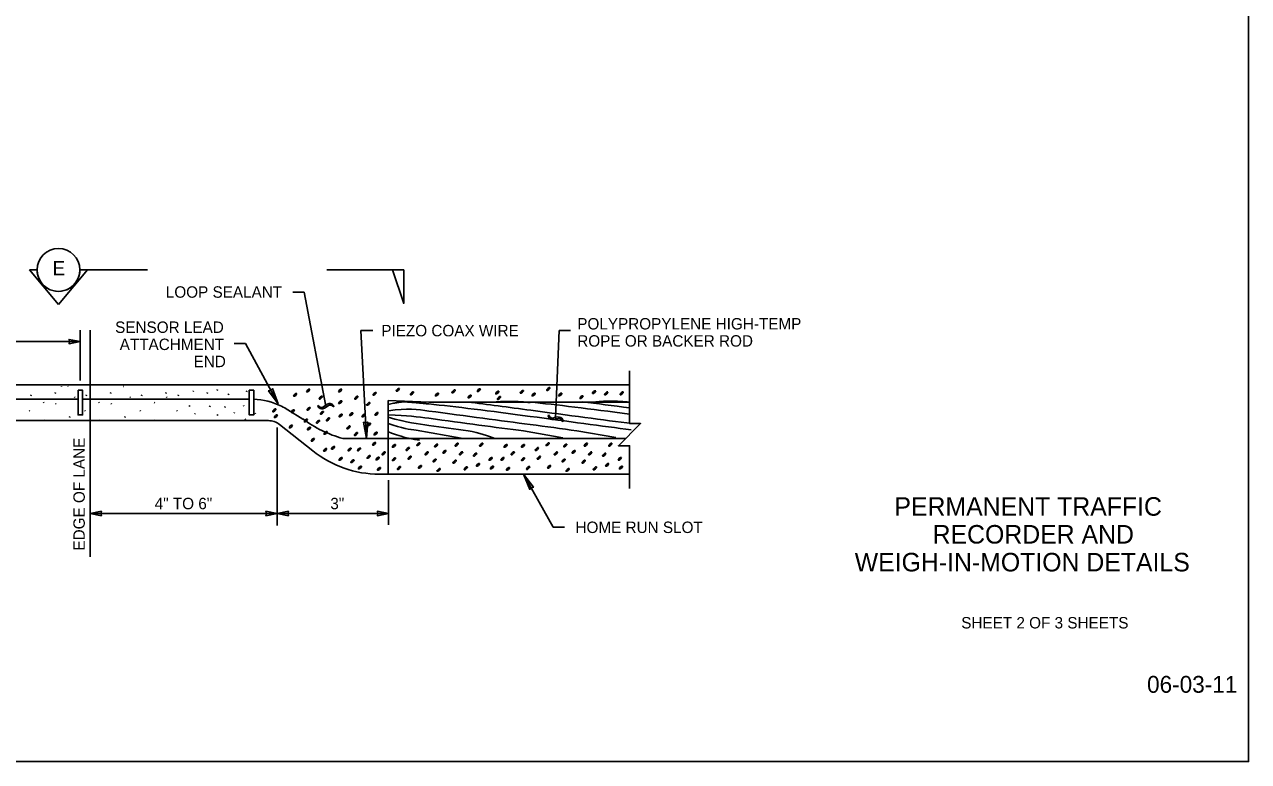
# Model space of a CAD drawing. Extents: x 99862 to 103151, y 100000 to 108076.
# Drawn here: x 101437 to 103151, y 103000 to 104032 of the extents above; entities that cross this region are included whole.
import ezdxf

# ---------------------------------------------------------------- set-up
doc = ezdxf.new("R2010")
doc.units = 0
for name, color, linetype in [('Level 1', 7, 'Continuous'), ('Level 15', 7, 'Continuous'), ('Level 16', 7, 'Continuous'), ('Level 2', 7, 'Continuous'), ('Level 20', 7, 'Continuous'), ('Level 32', 7, 'Continuous'), ('Level 33', 7, 'Continuous'), ('Level 5', 7, 'Continuous'), ('Level 6', 7, 'Continuous'), ('Level 62', 7, 'Continuous'), ('Level 9', 7, 'Continuous')]:
    doc.layers.add(name, color=color, linetype=linetype)

msp = doc.modelspace()

# ---------------------------------------------------------------- linework, layer by layer
at = {"layer": 'Level 1'}
msp.add_lwpolyline([(99862, 102999.5), (103151, 102999.5), (103151, 105075.5), (99862, 105075.5)], close=True, dxfattribs=at)
at = {"layer": 'Level 15'}
for p, q in [((101828.2, 103657), (101812.2, 103657)), ((101828.2, 103657), (101858.6, 103497.2)), ((101514.7, 103603.8), (101514.7, 103533.3)), ((101915.6, 103452), (101907.5, 103603.1)), ((101907.5, 103603.1), (101924.3, 103603.1)), ((102180.5, 103480.3), (102185.4, 103603.1)), ((102185.4, 103603.1), (102201.4, 103603.1)), ((101514.7, 103587.8), (101219.3, 103587.8)), ((101746, 103585.1), (101730, 103585.1)), ((101792, 103500.4), (101746, 103585.1)), ((101511.6, 103519.6), (101517.8, 103519.6)), ((101511.6, 103519.6), (101511.6, 103507.1)), ((101517.8, 103519.6), (101517.8, 103485)), ((101757.6, 103519.6), (101757.6, 103485)), ((101945.8, 103505.3), (101945.8, 103447.2)), ((101790.5, 103467.2), (101790.5, 103330.2)), ((101945.8, 103447.2), (101945.8, 103402)), ((102135.4, 103402), (102177.2, 103327.8)), ((101946.5, 103393.7), (101946.5, 103330.9)), ((101790.5, 103346.9), (101528.5, 103346.9)), ((101946.5, 103346.9), (101790.5, 103346.9)), ((102193, 103327.8), (102177.2, 103327.8))]:
    msp.add_line(p, q, dxfattribs=at)
for points in [[(101514.7, 103587.8), (101498.9, 103584.7), (101499.7, 103587.8), (101498.9, 103590.9)], [(101792, 103500.4), (101778.5, 103519), (101781.6, 103519.5), (101783.8, 103521.9)], [(101915.6, 103452), (101911.4, 103474.7), (101914.5, 103473.8), (101917.4, 103475)], [(102135.4, 103402), (102144.3, 103380.7), (102146.3, 103383.1), (102149.4, 103383.7)], [(101528.5, 103346.9), (101544.2, 103343.8), (101543.5, 103346.9), (101544.2, 103350)], [(101790.5, 103346.9), (101774.8, 103343.8), (101775.5, 103346.9), (101774.8, 103350)], [(101790.5, 103346.9), (101806.2, 103343.8), (101805.5, 103346.9), (101806.2, 103350)], [(101946.5, 103346.9), (101930.8, 103343.8), (101931.5, 103346.9), (101930.8, 103350)]]:
    msp.add_lwpolyline(points, close=True, dxfattribs=at)
msp.add_lwpolyline([(102284, 103547), (102284, 103472.9), (102299.5, 103472.9), (102268.5, 103441.9), (102284, 103441.9), (102284, 103382)], dxfattribs=at)
at = {"layer": 'Level 16'}
for p, q in [((101945.8, 103505.3), (102003, 103502.9)), ((102003, 103502.9), (102144.7, 103502.9)), ((102144.8, 103503.1), (102284, 103503.1)), ((101950.5, 103459.5), (101946.4, 103461.2)), ((101985.2, 103463.5), (102048.1, 103452.6)), ((102135.7, 103462.6), (102190.7, 103452.8)), ((102210.3, 103462.8), (102264.7, 103453.3))]:
    msp.add_line(p, q, dxfattribs=at)
for points, degree in [([(101946.1, 103499.7), (101963.8, 103503.7), (101970.5, 103503.3), (101977.5, 103502.8), (101985, 103502.2), (101993.5, 103501.4), (102003, 103500.4)], 4), ([(102057.5, 103503), (102084.6, 103499.7), (102114.3, 103495.8), (102145.9, 103491.6)], 3), ([(102095.1, 103502.9), (102107.4, 103504.3), (102122.4, 103504.1), (102139.5, 103502.8), (102141.1, 103502.7), (102142.9, 103502.5), (102144.6, 103502.4)], 4), ([(102144.8, 103503.1), (102181.2, 103499.4), (102228.4, 103493.4), (102284, 103486.1)], 3), ([(102217.7, 103503.4), (102238.7, 103500.8), (102260.9, 103497.9), (102284, 103494.8)], 3), ([(102236.9, 103503.3), (102249.2, 103504.6), (102264.2, 103504.5), (102281.3, 103503.1), (102282.2, 103503), (102283.1, 103503), (102284, 103502.9)], 4), ([(101946.3, 103490.8), (101972.4, 103494.6), (101987.6, 103492.6), (102003, 103490.5)], 3), ([(102003, 103500.4), (102040, 103496.7), (102088.1, 103490.5), (102144.8, 103483)], 3), ([(102003, 103490.5), (102055.9, 103483.4), (102104.2, 103476.8), (102144.8, 103471.6)], 3), ([(102145.9, 103491.6), (102198.8, 103484.6), (102247.1, 103477.9), (102287.8, 103472.8)], 3), ([(101945.7, 103473.1), (101966.1, 103465.9), (101976, 103464.6), (101985.2, 103463.5)], 3), ([(101946, 103481.7), (101972.6, 103474.3), (101987.7, 103472.3), (102003, 103470.2)], 3), ([(101946.6, 103485.3), (101972.4, 103484.4), (101987.6, 103482.4), (102003, 103480.3)], 3), ([(102003, 103480.3), (102051.6, 103473.8), (102096.7, 103467.6), (102135.7, 103462.6)], 3), ([(102003, 103470.2), (102021.5, 103467.8), (102039.9, 103465.3), (102057.9, 103462.9)], 3), ([(102144.8, 103483), (102197.5, 103476), (102245.8, 103469.3), (102286.5, 103464.2)], 3), ([(102144.8, 103471.6), (102167.1, 103468.7), (102189, 103465.7), (102210.3, 103462.8)], 3), ([(101950.5, 103459.5), (101970.8, 103452.2), (101980.7, 103451), (101989.9, 103449.8)], 3), ([(102057.9, 103462.9), (102074.2, 103459.8), (102085.7, 103456), (102095.5, 103451.9)], 3), ([(101945.2, 103450.6), (101945.4, 103450.5), (101945.6, 103450.5), (101945.8, 103450.4)], 3)]:
    msp.add_open_spline(points, degree=degree, dxfattribs=at)
at = {"layer": 'Level 2'}
for p, q in [((101528.5, 103603.9), (101528.5, 103286)), ((101328.2, 103527), (101635, 103527)), ((101635, 103527), (102284, 103527)), ((101326.7, 103477), (101635, 103477)), ((101635, 103477), (101778.2, 103477)), ((101793.8, 103471.6), (101840.2, 103434.6)), ((101928.8, 103402), (102284, 103402))]:
    msp.add_line(p, q, dxfattribs=at)
for centre, radius, start, end in [((101778.2, 103452), 25, 51.4993, 90), ((101933.6, 103552), 150, 231.4993, 270)]:
    msp.add_arc(centre, radius, start, end, dxfattribs=at)
at = {"layer": 'Level 20'}
for p, q in [((101849.4, 103496.7), (101847.4, 103498.2)), ((101847.4, 103498.2), (101847.8, 103496.1)), ((101847.8, 103496.1), (101849.3, 103494.8)), ((101849.3, 103494.8), (101850.8, 103493.9)), ((101850.9, 103495.9), (101849.4, 103496.7)), ((101850.8, 103493.9), (101852.5, 103493.5)), ((101852.2, 103495.5), (101850.9, 103495.9)), ((101853.5, 103495.6), (101852.2, 103495.5)), ((101852.5, 103493.5), (101854.2, 103493.5)), ((101855.3, 103496.2), (101853.5, 103495.6)), ((101854.2, 103493.5), (101856.8, 103494.5)), ((101857.4, 103497.7), (101855.3, 103496.2)), ((101856.8, 103494.5), (101860.4, 103497)), ((101860.7, 103500.1), (101857.4, 103497.7)), ((101860.4, 103497), (101862.4, 103498.4)), ((101863.1, 103500.9), (101860.7, 103500.1)), ((101862.4, 103498.4), (101863.8, 103498.8)), ((101864.7, 103500.9), (101863.1, 103500.9)), ((101863.8, 103498.8), (101865.2, 103498.8)), ((101866.3, 103500.5), (101864.7, 103500.9)), ((101865.2, 103498.8), (101866.8, 103498.3)), ((101867.9, 103499.7), (101866.3, 103500.5)), ((101866.8, 103498.3), (101869.8, 103496.2)), ((101869.5, 103498.3), (101867.9, 103499.7)), ((101869.8, 103496.2), (101869.5, 103498.3)), ((102170.4, 103485.3), (102170, 103483.2)), ((102170, 103483.2), (102171, 103481.3)), ((102172.5, 103482.2), (102170.4, 103485.3)), ((102171, 103481.3), (102172.1, 103480)), ((102172.1, 103480), (102173.5, 103479)), ((102173.8, 103481.2), (102172.5, 103482.2)), ((102173.5, 103479), (102175, 103478.5)), ((102175.1, 103480.6), (102173.8, 103481.2)), ((102175, 103478.5), (102177.5, 103478.4)), ((102176.6, 103480.6), (102175.1, 103480.6)), ((102178.9, 103481.2), (102176.6, 103480.6)), ((102177.5, 103478.4), (102181.5, 103479.4)), ((102183.2, 103482.2), (102178.9, 103481.2)), ((102181.5, 103479.4), (102183.9, 103480)), ((102185.9, 103482.1), (102183.2, 103482.2)), ((102183.9, 103480), (102185.9, 103480)), ((102187.6, 103481.5), (102185.9, 103482.1)), ((102185.9, 103480), (102187.1, 103479.5)), ((102187.1, 103479.5), (102188.2, 103478.7)), ((102189, 103480.6), (102187.6, 103481.5)), ((102188.2, 103478.7), (102189.3, 103477.4)), ((102190.1, 103479.2), (102189, 103480.6)), ((102189.3, 103477.4), (102190.6, 103475.3)), ((102191, 103477.4), (102190.1, 103479.2)), ((102190.6, 103475.3), (102191, 103477.4))]:
    msp.add_line(p, q, dxfattribs=at)
at = {"layer": 'Level 32'}
for centre in [(101833.9, 103519.2), (101878.7, 103519.2), (101959.5, 103520.3), (102037.5, 103518.1), (102072.9, 103519.7), (102133.2, 103517.5), (102170.3, 103521.4), (101815.7, 103513.1), (101851.6, 103509.2), (101878.8, 103502.8), (101901.4, 103509.2), (101918, 103500.4), (101926.9, 103514.7), (101979.4, 103515.3), (102014.3, 103513.6), (102060.2, 103510.9), (102098.9, 103516.4), (102101.1, 103508.7), (102149.8, 103513.6), (102186.9, 103513.6), (102216.7, 103509.8), (102234.4, 103517), (102251.3, 103515.2), (102273.1, 103515.3), (101786.4, 103491.5), (101788.6, 103483.2), (101812.4, 103490.4), (101834.5, 103493.7), (101853.3, 103488.1), (101879.3, 103484.3), (101894.2, 103486), (101911.4, 103484.3), (101929.6, 103486.5), (101809.6, 103468.8), (101830.6, 103477.1), (101835, 103466.1), (101847.8, 103475.5), (101861.6, 103478.8), (101890.4, 103467.7), (101919.1, 103471.6), (101840.4, 103450.1), (101858.3, 103460), (101900.9, 103458.3), (101928.5, 103458.9), (101857.7, 103436.2), (101868.8, 103439), (101892, 103436.7), (101905.3, 103436.7), (101926.3, 103444.5), (101954, 103441.7), (101973.4, 103437.3), (101988.3, 103443.9), (102013.2, 103442.3), (102024.8, 103433.4), (102042, 103443.4), (102076.3, 103443.4), (102110.5, 103441.7), (102134.9, 103441.7), (102154.2, 103437.3), (102169.2, 103443.9), (102194, 103442.3), (102205.7, 103433.4), (102222.8, 103443.4), (102257.1, 103443.4), (101879.3, 103423.5), (101895.9, 103420.1), (101918.6, 103426.2), (101931.3, 103424), (101939.6, 103431.2), (101954, 103422.9), (101976.1, 103425.1), (101999.9, 103431.2), (102011, 103421.3), (102038.9, 103419.5), (102048.1, 103431.2), (102067.7, 103429.4), (102071.8, 103415.2), (102089.5, 103423.5), (102106.1, 103423.5), (102120.5, 103431.2), (102134.9, 103422.9), (102157, 103425.1), (102180.8, 103431.2), (102191.8, 103421.3), (102219.8, 103419.5), (102228.9, 103431.2), (102248.5, 103429.4), (102252.7, 103415.2), (102270.4, 103423.5), (101906.4, 103411.3), (101933, 103409.6), (101961.2, 103410.7), (101990.5, 103412.4), (102016.5, 103408), (102054.7, 103410.2), (102091.2, 103411.3), (102113.8, 103409.6), (102142, 103410.7), (102171.4, 103412.4), (102197.4, 103408), (102235.5, 103410.2), (102272, 103411.3)]:
    msp.add_ellipse(centre, major_axis=(2.21, 1.94), ratio=0.362832, dxfattribs=at)
at = {"layer": 'Level 33'}
for p, q in [((101488.3, 103525.2), (101488.4, 103525)), ((101497.3, 103525.2), (101497.6, 103524.7)), ((101574.9, 103525), (101575.1, 103524.7)), ((101706.3, 103519.4), (101706.8, 103520.7)), ((101445.2, 103511.9), (101445.8, 103513.2)), ((101463.2, 103502.7), (101463.8, 103501.9)), ((101479.3, 103515.2), (101479.9, 103516.5)), ((101506.7, 103510.3), (101507.2, 103509.4)), ((101522.8, 103511.9), (101523.4, 103513.2)), ((101540.8, 103502.7), (101541.3, 103501.9)), ((101556.9, 103515.2), (101557.4, 103516.5)), ((101584.2, 103510.3), (101584.8, 103509.4)), ((101600.3, 103511.9), (101600.9, 103513.2)), ((101634.4, 103515.2), (101635, 103516.5)), ((101635.5, 103510.3), (101636.1, 103509.4)), ((101651.6, 103511.9), (101652.2, 103513.2)), ((101672.7, 103517.7), (101673.3, 103519)), ((101692.3, 103514.9), (101692.9, 103516.2)), ((101722, 103513.1), (101722.6, 103514.4)), ((101747.5, 103517.3), (101748, 103518.6)), ((101443.3, 103491), (101443.9, 103490.1)), ((101480.2, 103501.2), (101480.8, 103500.3)), ((101520.9, 103491), (101521.4, 103490.1)), ((101557.8, 103501.2), (101558.3, 103500.3)), ((101598.4, 103491), (101599, 103490.1)), ((101618.4, 103502.6), (101618.9, 103501.9)), ((101649.7, 103491), (101650.3, 103490.1)), ((101667.4, 103497), (101668, 103498.3)), ((101675.2, 103485.9), (101675.8, 103487.2)), ((101695.8, 103496.4), (101696.4, 103497.7)), ((101717.1, 103495.3), (101717.7, 103496.6)), ((101730, 103487.3), (101730.6, 103488.6)), ((101743.1, 103498), (101743.7, 103497.1)), ((101759.5, 103487.5), (101760.1, 103486.6)), ((101463.8, 103478.2), (101464.3, 103477.3)), ((101499.5, 103481.3), (101500, 103482.6)), ((101541.3, 103478.2), (101541.9, 103477.3)), ((101577, 103481.3), (101577.6, 103482.6)), ((101618.8, 103478.2), (101619.4, 103477.3)), ((101706.6, 103484.2), (101707.2, 103485.4)), ((101745.5, 103479.5), (101746.1, 103478.6))]:
    msp.add_line(p, q, dxfattribs=at)
at = {"layer": 'Level 5'}
for p, q in [((101326.7, 103507.2), (101511.6, 103507.2)), ((101517.8, 103507.2), (101625.2, 103507.2)), ((101625.2, 103507.2), (101635, 103507.2)), ((101635, 103507.2), (101751.4, 103507.2))]:
    msp.add_line(p, q, dxfattribs=at)
msp.add_arc((101752.9, 103407.2), 100, 64.1343, 87.3109, dxfattribs=at)
at = {"layer": 'Level 6'}
for p, q in [((101805.5, 103492.3), (101826.5, 103479.3)), ((101882.5, 103452), (101945.8, 103452)), ((101945.8, 103452), (102278.7, 103452))]:
    msp.add_line(p, q, dxfattribs=at)
for points in [[(101511.6, 103519.6), (101517.8, 103519.6), (101517.8, 103485), (101511.6, 103485)], [(101751.4, 103519.6), (101757.6, 103519.6), (101757.6, 103485), (101751.4, 103485)]]:
    msp.add_lwpolyline(points, close=True, dxfattribs=at)
for centre, radius, start, end in [((101752.9, 103407.2), 100, 58.286, 64.1343), ((101926.9, 103614.3), 168.2, 233.3536, 254.7115)]:
    msp.add_arc(centre, radius, start, end, dxfattribs=at)
at = {"layer": 'Level 9'}
for p, q in [((101454.1, 103688.1), (101443.5, 103688.1)), ((101443.5, 103688.1), (101484.1, 103639.7)), ((101484.1, 103639.7), (101524.7, 103688.1)), ((101524.7, 103688.1), (101514.1, 103688.1)), ((101514.1, 103688.1), (101608.9, 103688.1)), ((101859.9, 103688.1), (101967.8, 103688.1))]:
    msp.add_line(p, q, dxfattribs=at)
msp.add_lwpolyline([(101952.2, 103688.1), (101967.8, 103641.2), (101967.8, 103688.1)], close=True, dxfattribs=at)
msp.add_circle((101484.1, 103688.1), 30, dxfattribs=at)
msp.add_arc((101484.1, 103688.1), 30, 179.9978, 0.0022, dxfattribs=at)

# ---------------------------------------------------------------- texts
at = {"layer": 'Level 15'}
msp.add_text('06-03-11', height=23.62, dxfattribs=at).set_placement((103008.9, 103095.8))
at = {"layer": 'Level 20'}
for s, height, rotation, p in [('E', 20, 360, (101475.8, 103680.5)), ('LOOP SEALANT', 16, 360, (101634.5, 103649.2)), ('SENSOR LEAD', 16, 360, (101563.5, 103599.9)), ('PIEZO COAX WIRE', 16, 360, (101936.3, 103595.1)), ('POLYPROPYLENE HIGH-TEMP', 16, 360, (102210.8, 103604.7)), ('ATTACHMENT', 16, 360, (101569.9, 103575.9)), ('ROPE OR BACKER ROD', 16, 360, (102210.8, 103580.7)), ('END', 16, 360, (101673.4, 103551.9)), ('EDGE OF LANE', 16, 90, (101521, 103295)), ('4" TO 6"', 16, 360, (101618.9, 103352.9)), ('3" ', 16, 360, (101864.9, 103352.9))]:
    msp.add_text(s, height=height, rotation=rotation, dxfattribs=at).set_placement(p)
msp.add_text('HOME RUN SLOT', height=16, dxfattribs=at).set_placement((102208.3, 103319.6))
at = {"layer": 'Level 62'}
for s, height, p in [('PERMANENT TRAFFIC', 26, (102655, 103343.8)), ('RECORDER AND ', 26, (102708.5, 103304.8)), ('WEIGH-IN-MOTION DETAILS', 26, (102599.4, 103265.8)), ('SHEET 2 OF 3 SHEETS', 16, (102748.6, 103185.9))]:
    msp.add_text(s, height=height, dxfattribs=at).set_placement(p)

doc.saveas('drawing.dxf')
